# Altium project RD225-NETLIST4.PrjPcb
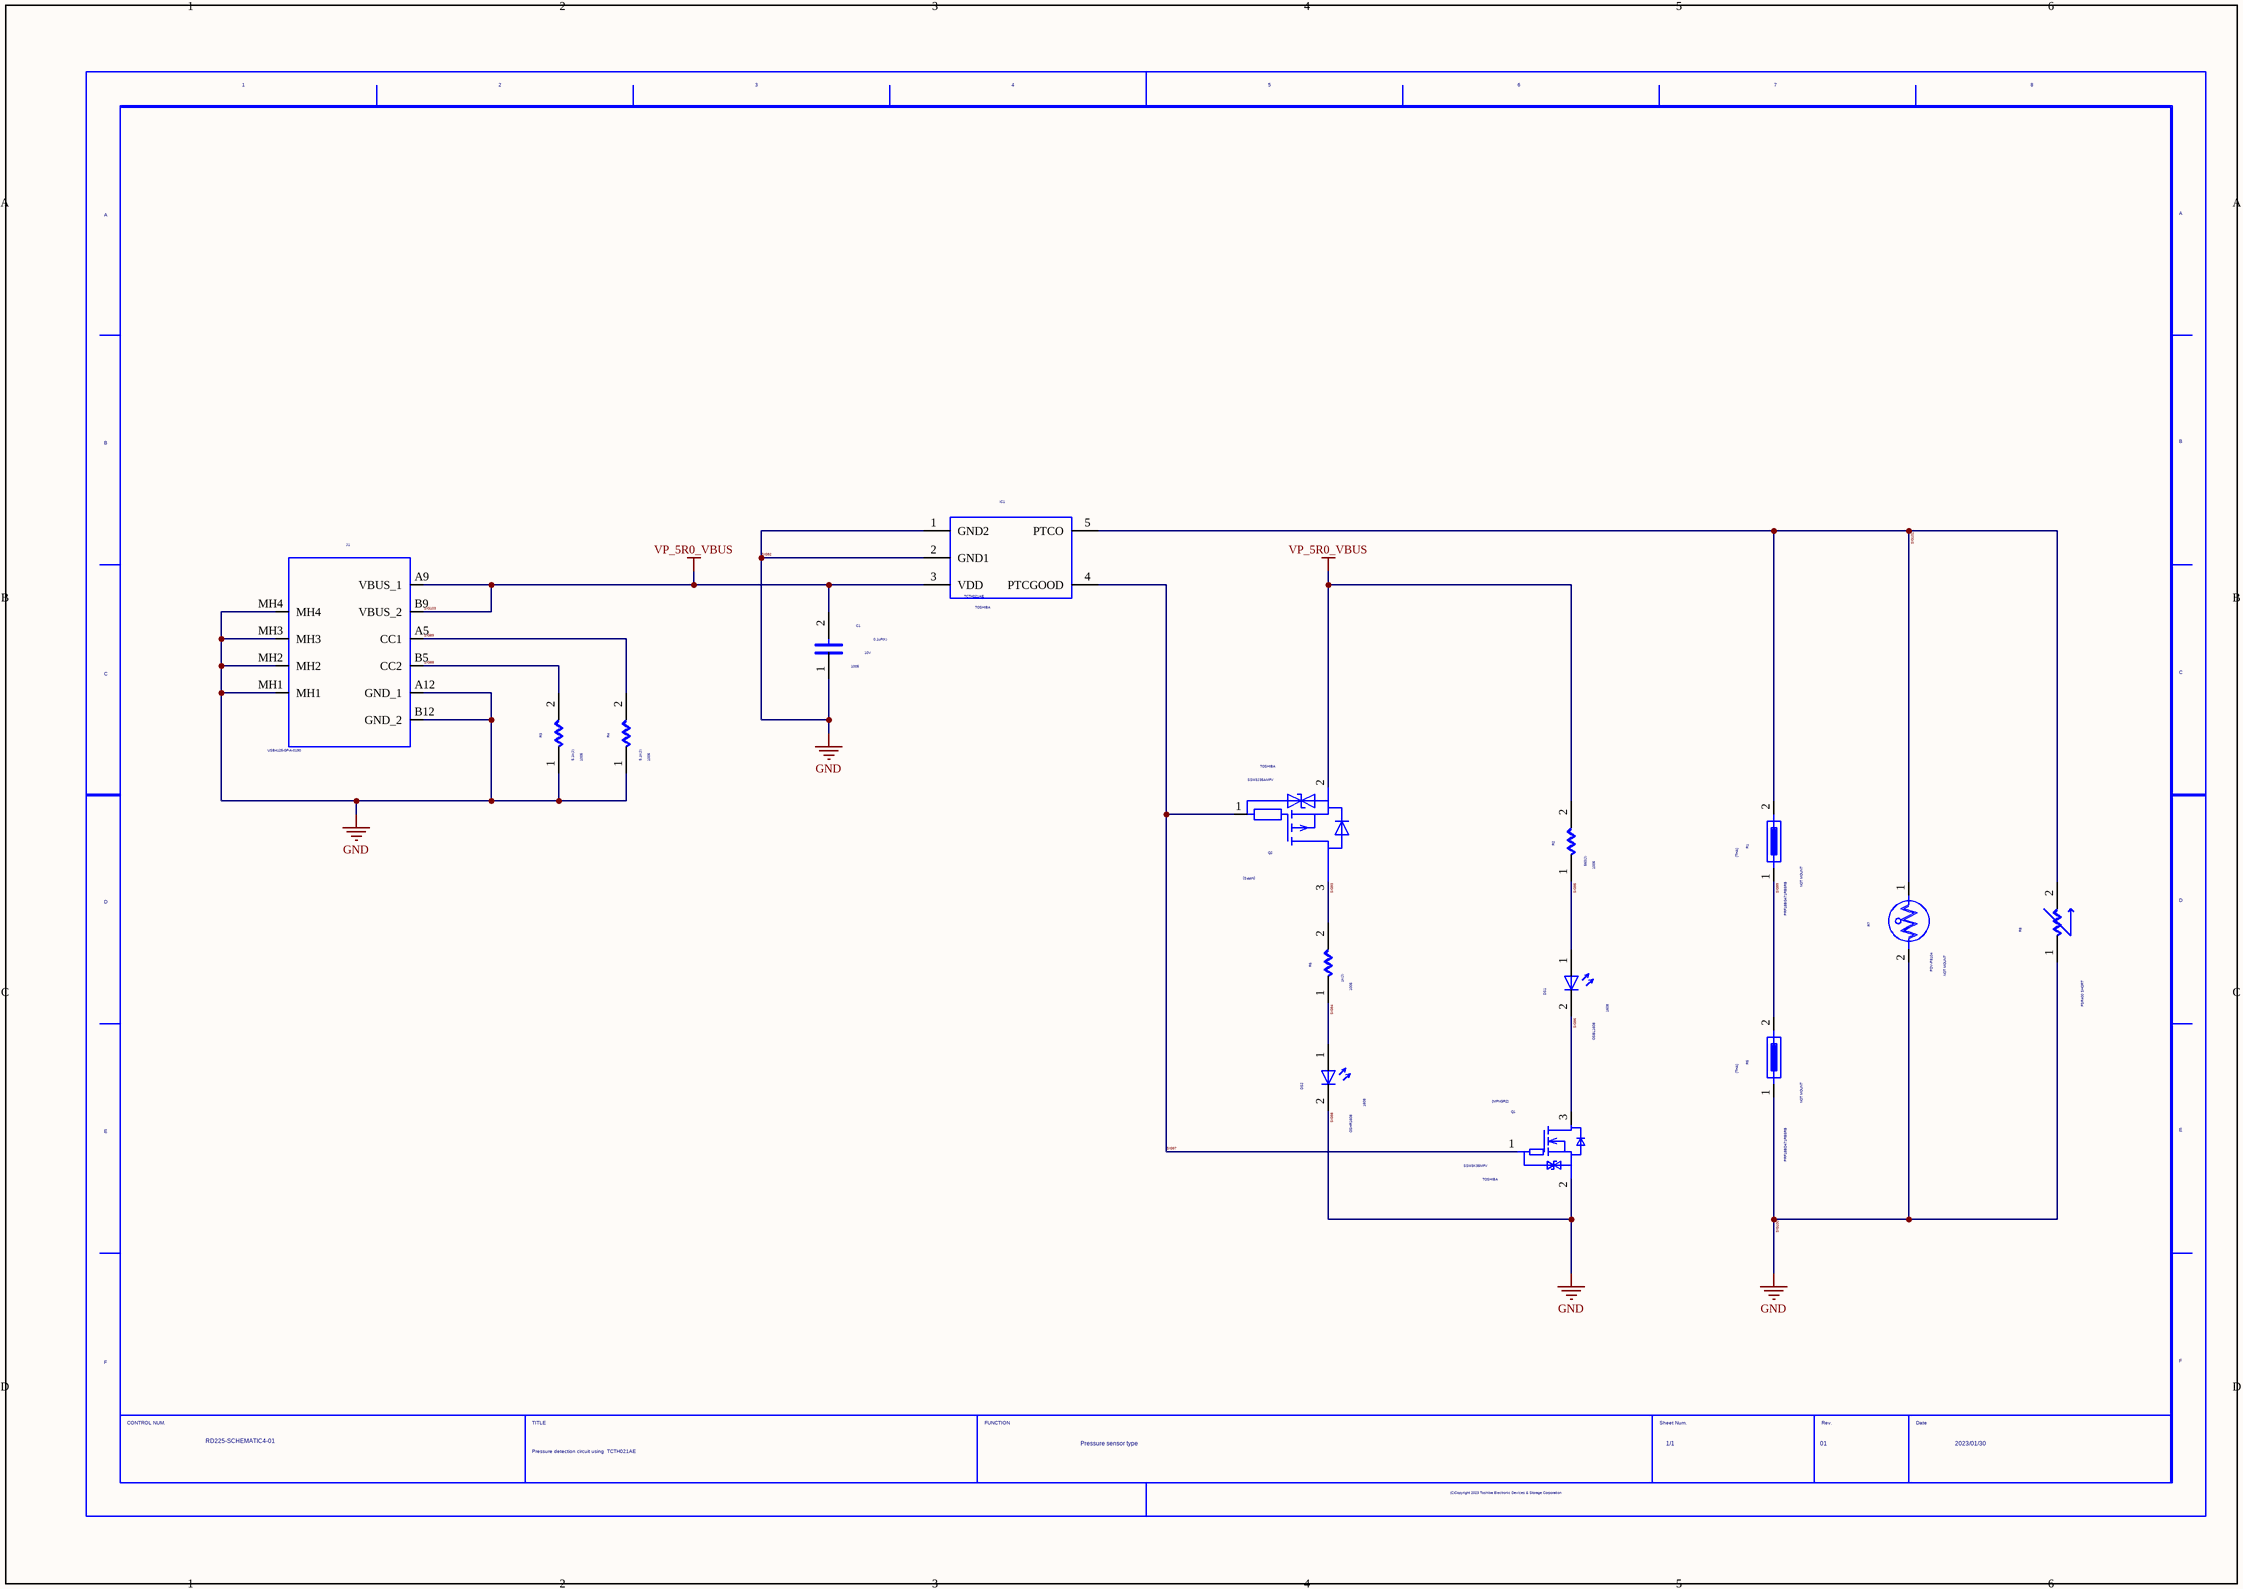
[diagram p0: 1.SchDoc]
1 sheet, 16 parts. Net scope: global (net labels, ports and power ports of the same name join across sheets).

## Sheet 1.SchDoc
size 420 x 297 mm

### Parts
C1  SIZECODESMD: 1005  VAL2: 10V  VAL1: 0.1uF(K)  (hidden comment: C)
DS1  SIZECODESMD: 1608  VAL3: OSBL1608  (hidden comment: LED)
DS2  SIZECODESMD: 1608  VAL3: OSHR1608  (hidden comment: LED)
IC1  USERCOMPTEXT3: TOSHIBA  (hidden comment: TCTH021AE)
J1  USB4125-GF-A-0190
Q1  VAL3: SSM3K35MFV  USERCOMPTEXT3: TOSHIBA  (hidden comment: MFNGR2)
Q2  USERCOMPTEXT3: TOSHIBA  VAL3: SSM3J35AMFV  (hidden comment: MFPS)
R1  NOTMOUNT: NOT MOUNT  VAL3: PRF18BG471RB5RB  (hidden comment: THA)
R2  SIZECODESMD: 1005  VAL1: 560(J)  (hidden comment: R)
R3  SIZECODESMD: 1005  VAL1: 5.1k(J)  (hidden comment: R)
R4  SIZECODESMD: 1005  VAL1: 5.1k(J)  (hidden comment: R)
R5  NOTMOUNT: NOT MOUNT  VAL3: PRF18BD471RB5RB  (hidden comment: THA)
R6  SIZECODESMD: 1005  VAL1: 1k(J)  (hidden comment: R)
R7  NOTMOUNT: NOT MOUNT  VAL3: PDV-P8104  (hidden comment: HM-ERTJ0P473)
R8  VAL3: FSR400 SHORT  (hidden comment: FSR400)
U?  DATE: 2023/01/30  TITLE: Pressure detection circuit using / TCTH021AE  REVISION: 01  SHEETNUMBER: 1/1  FUNCTION: Pressure sensor type  DRAWINGNUMBER: RD225-SCHEMATIC4-01  (hidden comment: WAKU_DEF100)

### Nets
SIG100: C1.1 DS2.2(C) IC1.1(GND2) IC1.2(GND1) J1.A12(GND_1) J1.B12(GND_2) J1.MH1 J1.MH2 J1.MH3 J1.MH4 Q1.2(S) R3.1 R4.1 R5.1 R7.2 R8.1  [also labelled GND, SIG92, SIG98]
SIG103: C1.2 IC1.3(VDD) J1.A9(VBUS_1) J1.B9(VBUS_2) Q2.2(S) R2.2  [also labelled VP_5R0_VBUS]
SIG88: J1.B5(CC2) R3.2
SIG89: J1.A5(CC1) R4.2
SIG93: Q2.3(D) R6.2
SIG94: DS2.1(A) R6.1
SIG95: DS1.1(A) R2.1
SIG96: DS1.2(C) Q1.3(D)
SIG97: IC1.4(PTCGOOD) Q1.1(G) Q2.1(G)
SIG99: R1.1 R5.2
SIG102: IC1.5(PTCO) R1.2 R7.1 R8.2

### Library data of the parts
C1 = C: OriginalSymbolOrigin: (2540,7620)
DS1 DS2 = LED: SAVEAREA0: -6799,-183,19247,15664; TIME: 14:49:55; UPDATEUSER: fukuda-y; UPDATETIME: 13:54:07; SAVECOUNT: 4; OriginalSymbolOrigin: (5080,7620)
IC1 = TCTH021AE: SAVEAREA0: -21868,-8311,47688,23382; TIME: 17:28:34; UPDATEUSER: PS4_common_PC; UPDATETIME: 17:38:33; SAVECOUNT: 2; OriginalSymbolOrigin: (5080,15240)
J1 = USB4125-GF-A-0190: TIME: 13:15:33; UPDATEUSER: t5459927; UPDATETIME: 17:07:21; SAVECOUNT: 7; SAVEAREA0: -96519,-35138,112864,60268; OriginalSymbolOrigin: (0,35560)
Q1 = MFNGR2: SAVECOUNT: 25; SAVEAREA0: -9479,-3469,21984,16316; TIME: 16:49:03; UPDATEUSER: tomizawa-y; UPDATETIME: 16:24:51; OriginalSymbolOrigin: (0,10160)
Q2 = MFPS: SAVECOUNT: 24; SAVEAREA0: -2907,-251,25408,18358; TIME: 08:01:03; UPDATEUSER: sato-yr; UPDATETIME: 15:10:02; OriginalSymbolOrigin: (2540,17780)
R1 = THA: SAVECOUNT: 3; SAVEAREA0: -562,-143,15615,10489; TIME: 16:37:29; UPDATEUSER: sato-yr; OriginalSymbolOrigin: (2540,5080)
R2-R4 R6 = R: OriginalSymbolOrigin: (5080,5080); VAL2: 100mW
R5 = THA: SAVECOUNT: 3; SAVEAREA0: -562,-143,15615,10489; TIME: 16:37:29; UPDATEUSER: sato-yr; OriginalSymbolOrigin: (2540,5080); OLDCOMPONENTID: 399
R7 = HM-ERTJ0P473: CDBNAME: R; MONOCODE: E00000368; DEVICENAME: ERTJ0EP473H; SAVECOUNT: 7; SAVEAREA0: -34062,-18143,50567,39798; TIME: 17:24:52; UPDATEUSER: Administrator; UPDATETIME: 15:47:22; OriginalSymbolOrigin: (2540,5080); COMP: CDS
R8 = FSR400: SAVEAREA0: -12454,-13119,45493,18589; TIME: 12:32:26; UPDATEUSER: t5459927; SAVECOUNT: 1; OriginalSymbolOrigin: (10160,12700); COMP: FSR400_SHORT
U? = WAKU_DEF100: PLOTTIME: HH:MM; SAVEAREA0: 22200,72372,612276,319236; TIME: 14:30:25; UPDATEUSER: PS4_common_PC; UPDATETIME: 17:48:40; SAVECOUNT: 7; OriginalSymbolOrigin: (10160,284480)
